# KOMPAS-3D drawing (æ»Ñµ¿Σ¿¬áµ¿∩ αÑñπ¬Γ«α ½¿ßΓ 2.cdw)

Referenced files: 2.cdw
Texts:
  ПЛК.303120.01 СП
  Назаров
  Шайба 6 Л ГОСТ 6402-70
  Шайба пружинная
  Шайба
  ГОСТ
  Сборочный чертеж
  ПШП. РЧО.140.00.00 СБ-
  М12х1.25-6gx90.109.40X.016
  Гайки ГОСТ 5950-70
  Шайбы ГОСТ 6402-70
  Прокладка регулировочная
  Ст 10
  Картон технич.
  Паронит
  Болты ГОСТ 7798-75
  М12х1.25-6gx110.109.40X.016
  М10х1.25-6gx35.109.40X.016
  М10х1.25-6gx25.109.40X.016
  М8х1.25-6gx18.109.40X.016
  М6х1.25-6gx15.109.40X.016
  Рым-болт М10.19 ГОСТ 4751-73
  Манжета  ГОСТ 8752-78
  Подшипник 207 ГОСТ 8338-75
  Подшипник 210 ГОСТ 8338-75
  Стандартные изделия
  Подшипник 214 ГОСТ 8338-75
Dimensions and other numbers on the sheet: 65Г; 029; 70; 1:1; 1; 2; 23; 19; 20; 21; 22; 28; 29; 30; 32; 34; 35; 38; 39; 40; 41; 6; 4; 12; 25; 26; 27; 36; 8; 24; 31; 33; 37; 42; 12 ЛБрКМц3-1; 10 ЛБрКМц3-1; 8 ЛБрКМц3-1; 6 ЛБрКМц3-1; 0; 3; 5; 7; 9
